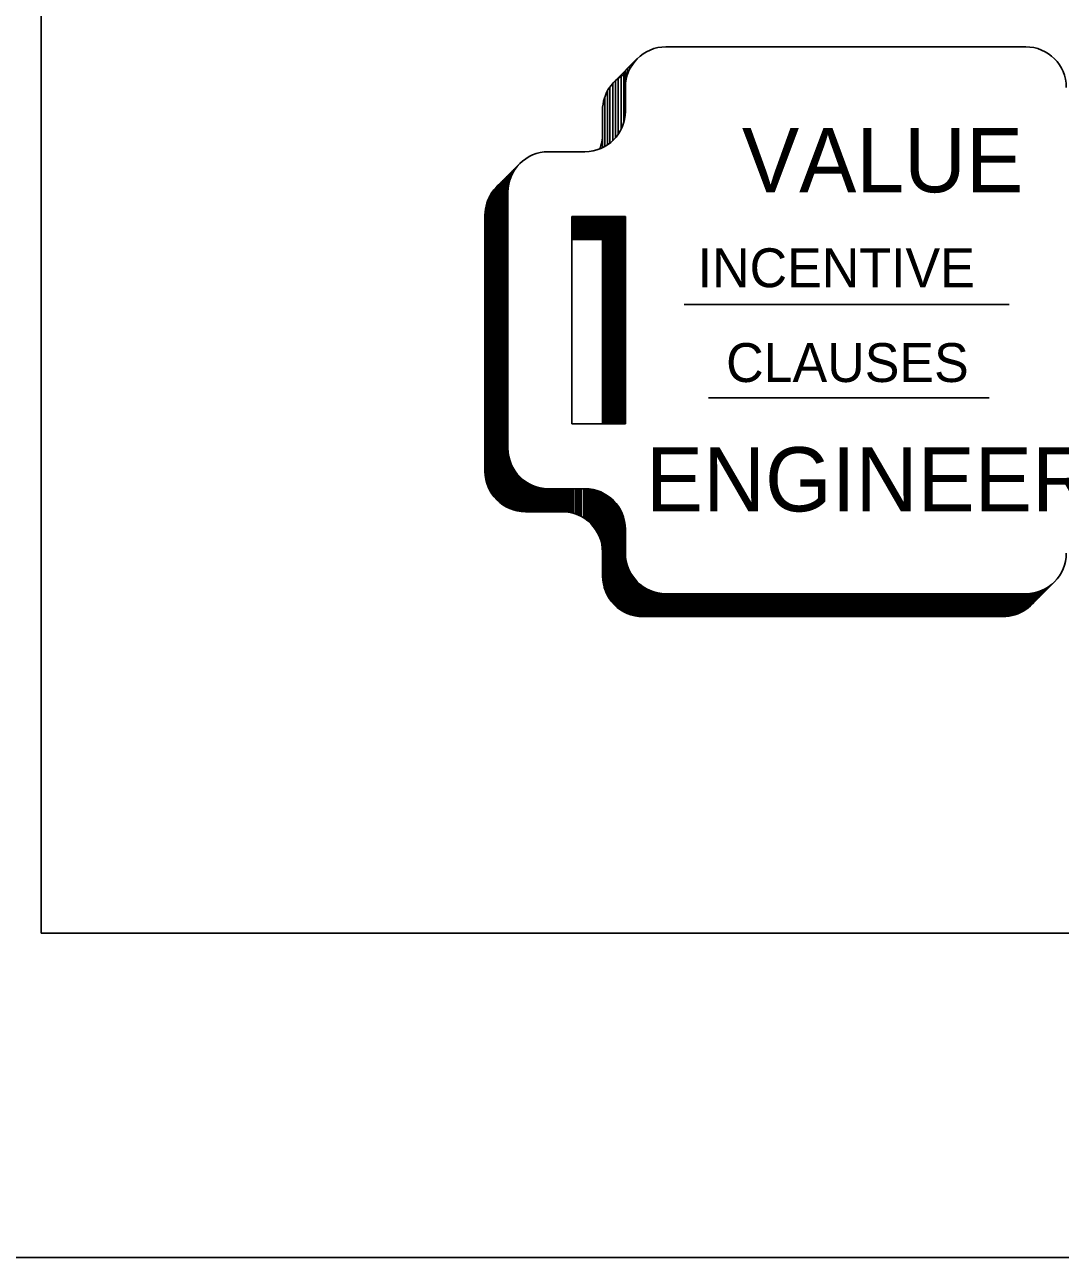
# Model space of a CAD drawing. Extents: x -11983 to -11903, y -13969.5 to -13913.5.
# Drawn here: x -11980.063 to -11976.865, y -13969.481 to -13965.677 of the extents above; entities that cross this region are included whole.
import ezdxf

# ---------------------------------------------------------------- set-up
doc = ezdxf.new("R2010")
doc.units = 0
doc.layers.add('Level 1', color=7, linetype='Continuous')
doc.layers.add('Level 2', color=7, linetype='Continuous')

msp = doc.modelspace()

# ---------------------------------------------------------------- linework, layer by layer
at = {"layer": 'Level 1'}
for points in [[(-11983.0122, -13913.481), (-11903.0122, -13913.481), (-11903.0122, -13969.481), (-11983.0122, -13969.481)], [(-11980.0122, -13914.481), (-11904.0122, -13914.481), (-11904.0122, -13968.481), (-11980.0122, -13968.481)]]:
    msp.add_lwpolyline(points, close=True, dxfattribs=at)
at = {"layer": 'Level 2'}
for p, q in [((-11976.9721, -13965.7456), (-11978.0831, -13965.7456)), ((-11978.2423, -13965.8529), (-11978.1716, -13965.7821)), ((-11978.1956, -13965.8161), (-11978.1956, -13965.8061)), ((-11978.1893, -13965.8049), (-11978.1893, -13965.7999)), ((-11978.1841, -13965.7969), (-11978.1841, -13965.7946)), ((-11978.2306, -13965.8411), (-11978.2306, -13966.0159)), ((-11978.2216, -13965.8321), (-11978.2216, -13966.0009)), ((-11978.2131, -13965.8236), (-11978.2131, -13965.9794)), ((-11978.2081, -13965.8706), (-11978.2081, -13965.8186)), ((-11978.2021, -13965.8324), (-11978.2021, -13965.8126)), ((-11978.2636, -13965.8816), (-11978.2636, -13966.0484)), ((-11978.2558, -13965.8691), (-11978.2558, -13966.0426)), ((-11978.2473, -13965.8584), (-11978.2473, -13966.0354)), ((-11978.2391, -13965.8496), (-11978.2391, -13966.0269)), ((-11978.2081, -13965.8706), (-11978.2081, -13965.9444)), ((-11978.2721, -13965.9009), (-11978.2721, -13966.0534)), ((-11978.2788, -13965.9414), (-11978.2788, -13966.0569)), ((-11978.3331, -13966.0694), (-11978.4461, -13966.0694)), ((-11978.6053, -13966.1766), (-11978.5346, -13966.1059)), ((-11978.5761, -13966.1474), (-11978.5761, -13967.1651)), ((-11978.5738, -13966.1451), (-11978.5738, -13967.1664)), ((-11978.5711, -13966.1944), (-11978.5711, -13966.1424)), ((-11978.5683, -13966.1684), (-11978.5683, -13966.1396)), ((-11978.5648, -13966.1554), (-11978.5648, -13966.1361)), ((-11978.5621, -13966.1479), (-11978.5621, -13966.1334)), ((-11978.5596, -13966.1421), (-11978.5596, -13966.1309)), ((-11978.5573, -13966.1374), (-11978.5573, -13966.1286)), ((-11978.5548, -13966.1326), (-11978.5548, -13966.1261)), ((-11978.5523, -13966.1286), (-11978.5523, -13966.1236)), ((-11978.5498, -13966.1246), (-11978.5498, -13966.1211)), ((-11978.5473, -13966.1211), (-11978.5473, -13966.1186)), ((-11978.6116, -13966.1836), (-11978.6116, -13967.1366)), ((-11978.6083, -13966.1799), (-11978.6083, -13967.1404)), ((-11978.6048, -13966.1764), (-11978.6048, -13967.1439)), ((-11978.6006, -13966.1719), (-11978.6006, -13967.1479)), ((-11978.5976, -13966.1689), (-11978.5976, -13967.1506)), ((-11978.5943, -13966.1656), (-11978.5943, -13967.1531)), ((-11978.5903, -13966.1616), (-11978.5903, -13967.1561)), ((-11978.5861, -13966.1574), (-11978.5861, -13967.1591)), ((-11978.5826, -13966.1539), (-11978.5826, -13967.1614)), ((-11978.5793, -13966.1506), (-11978.5793, -13967.1634)), ((-11978.6346, -13966.2231), (-11978.6346, -13967.0971)), ((-11978.6306, -13966.2134), (-11978.6306, -13967.1069)), ((-11978.6273, -13966.2066), (-11978.6273, -13967.1136)), ((-11978.6233, -13966.1996), (-11978.6233, -13967.1206)), ((-11978.6193, -13966.1936), (-11978.6193, -13967.1266)), ((-11978.6151, -13966.1879), (-11978.6151, -13967.1324)), ((-11978.5711, -13966.1944), (-11978.5711, -13966.9844)), ((-11978.6383, -13966.2359), (-11978.6383, -13967.0844)), ((-11978.6418, -13966.2651), (-11978.6418, -13967.0551)), ((-11978.2081, -13966.2694), (-11978.3736, -13966.2694)), ((-11978.3736, -13966.9094), (-11978.3736, -13966.2694)), ((-11978.2081, -13966.2726), (-11978.3736, -13966.2726)), ((-11978.2081, -13966.2759), (-11978.3736, -13966.2759)), ((-11978.2081, -13966.2796), (-11978.3736, -13966.2796)), ((-11978.2081, -13966.2834), (-11978.3736, -13966.2834)), ((-11978.2081, -13966.2874), (-11978.3736, -13966.2874)), ((-11978.2081, -13966.2911), (-11978.3736, -13966.2911)), ((-11978.2081, -13966.2949), (-11978.3736, -13966.2949)), ((-11978.2081, -13966.2989), (-11978.3736, -13966.2989)), ((-11978.2081, -13966.2694), (-11978.2788, -13966.3401)), ((-11978.2081, -13966.9094), (-11978.2081, -13966.2694)), ((-11978.2081, -13966.3024), (-11978.3736, -13966.3024)), ((-11978.2081, -13966.3061), (-11978.3736, -13966.3061)), ((-11978.2081, -13966.3099), (-11978.3736, -13966.3099)), ((-11978.2081, -13966.3134), (-11978.3736, -13966.3134)), ((-11978.2081, -13966.3169), (-11978.3736, -13966.3169)), ((-11978.2081, -13966.3199), (-11978.3736, -13966.3199)), ((-11978.2081, -13966.3236), (-11978.3736, -13966.3236)), ((-11978.2081, -13966.3266), (-11978.3736, -13966.3266)), ((-11978.2081, -13966.3299), (-11978.3736, -13966.3299)), ((-11978.2081, -13966.3329), (-11978.3736, -13966.3329)), ((-11978.2081, -13966.3366), (-11978.3736, -13966.3366)), ((-11978.2753, -13966.9094), (-11978.2753, -13966.3366)), ((-11978.2726, -13966.9094), (-11978.2726, -13966.3366)), ((-11978.2696, -13966.9094), (-11978.2696, -13966.3366)), ((-11978.2671, -13966.9094), (-11978.2671, -13966.3366)), ((-11978.2633, -13966.9094), (-11978.2633, -13966.3366)), ((-11978.2601, -13966.9094), (-11978.2601, -13966.3366)), ((-11978.2566, -13966.9094), (-11978.2566, -13966.3366)), ((-11978.2541, -13966.9094), (-11978.2541, -13966.3366)), ((-11978.2501, -13966.9094), (-11978.2501, -13966.3366)), ((-11978.2468, -13966.9094), (-11978.2468, -13966.3366)), ((-11978.2441, -13966.9094), (-11978.2441, -13966.3366)), ((-11978.2408, -13966.9094), (-11978.2408, -13966.3366)), ((-11978.2376, -13966.9094), (-11978.2376, -13966.3366)), ((-11978.2338, -13966.9094), (-11978.2338, -13966.3366)), ((-11978.2308, -13966.9094), (-11978.2308, -13966.3366)), ((-11978.2278, -13966.9094), (-11978.2278, -13966.3366)), ((-11978.2241, -13966.9094), (-11978.2241, -13966.3366)), ((-11978.2203, -13966.9094), (-11978.2203, -13966.3366)), ((-11978.2166, -13966.9094), (-11978.2166, -13966.3366)), ((-11978.2141, -13966.9094), (-11978.2141, -13966.3366)), ((-11978.2108, -13966.9094), (-11978.2108, -13966.3366)), ((-11978.2788, -13966.3401), (-11978.3736, -13966.3401)), ((-11978.2788, -13966.9094), (-11978.2788, -13966.3401)), ((-11978.0268, -13966.5411), (-11977.0231, -13966.5411)), ((-11977.9513, -13966.8291), (-11977.0851, -13966.8291)), ((-11978.2081, -13966.9094), (-11978.3736, -13966.9094)), ((-11978.5693, -13967.0051), (-11978.5693, -13967.1686)), ((-11978.5653, -13967.0219), (-11978.5653, -13967.1704)), ((-11978.5616, -13967.0321), (-11978.5616, -13967.1719)), ((-11978.5578, -13967.0404), (-11978.5578, -13967.1731)), ((-11978.5533, -13967.0486), (-11978.5533, -13967.1746)), ((-11978.5501, -13967.0536), (-11978.5501, -13967.1756)), ((-11978.5468, -13967.0584), (-11978.5468, -13967.1764)), ((-11978.5426, -13967.0639), (-11978.5426, -13967.1774)), ((-11978.5391, -13967.0679), (-11978.5391, -13967.1781)), ((-11978.5353, -13967.0719), (-11978.5353, -13967.1786)), ((-11978.5316, -13967.0756), (-11978.5316, -13967.1794)), ((-11978.5278, -13967.0789), (-11978.5278, -13967.1796)), ((-11978.5243, -13967.0819), (-11978.5243, -13967.1799)), ((-11978.5201, -13967.0851), (-11978.5201, -13967.1801)), ((-11978.5163, -13967.0879), (-11978.5163, -13967.1801)), ((-11978.5126, -13967.0901), (-11978.5126, -13967.1801)), ((-11978.5088, -13967.0924), (-11978.5088, -13967.1801)), ((-11978.5043, -13967.0949), (-11978.5043, -13967.1801)), ((-11978.5011, -13967.0966), (-11978.5011, -13967.1801)), ((-11978.4991, -13967.0976), (-11978.4991, -13967.1801)), ((-11978.4958, -13967.0991), (-11978.4958, -13967.1801)), ((-11978.4926, -13967.1004), (-11978.4926, -13967.1801)), ((-11978.4886, -13967.1019), (-11978.4886, -13967.1801)), ((-11978.4846, -13967.1034), (-11978.4846, -13967.1801)), ((-11978.4808, -13967.1044), (-11978.4808, -13967.1801)), ((-11978.4758, -13967.1059), (-11978.4758, -13967.1801)), ((-11978.4713, -13967.1069), (-11978.4713, -13967.1801)), ((-11978.4676, -13967.1076), (-11978.4676, -13967.1801)), ((-11978.4648, -13967.1079), (-11978.4648, -13967.1801)), ((-11978.4611, -13967.1084), (-11978.4611, -13967.1801)), ((-11978.4578, -13967.1089), (-11978.4578, -13967.1801)), ((-11978.4551, -13967.1091), (-11978.4551, -13967.1801)), ((-11978.4516, -13967.1094), (-11978.4516, -13967.1801)), ((-11978.4476, -13967.1094), (-11978.4476, -13967.1801)), ((-11978.4461, -13967.1094), (-11978.3331, -13967.1094)), ((-11978.4438, -13967.1094), (-11978.4438, -13967.1801)), ((-11978.4396, -13967.1094), (-11978.4396, -13967.1801)), ((-11978.4353, -13967.1094), (-11978.4353, -13967.1801)), ((-11978.4316, -13967.1094), (-11978.4316, -13967.1801)), ((-11978.4266, -13967.1094), (-11978.4266, -13967.1801)), ((-11978.4223, -13967.1094), (-11978.4223, -13967.1801)), ((-11978.4186, -13967.1094), (-11978.4186, -13967.1801)), ((-11978.4143, -13967.1094), (-11978.4143, -13967.1801)), ((-11978.4096, -13967.1094), (-11978.4096, -13967.1801)), ((-11978.4051, -13967.1094), (-11978.4051, -13967.1801)), ((-11978.4003, -13967.1094), (-11978.4003, -13967.1801)), ((-11978.3956, -13967.1094), (-11978.3956, -13967.1801)), ((-11978.3901, -13967.1094), (-11978.3901, -13967.1809)), ((-11978.3863, -13967.1094), (-11978.3863, -13967.1814)), ((-11978.3831, -13967.1094), (-11978.3831, -13967.1819)), ((-11978.3798, -13967.1094), (-11978.3798, -13967.1824)), ((-11978.3746, -13967.1094), (-11978.3746, -13967.1836)), ((-11978.3691, -13967.1094), (-11978.3691, -13967.1851)), ((-11978.3633, -13967.1094), (-11978.3633, -13967.1869)), ((-11978.3578, -13967.1094), (-11978.3578, -13967.1889)), ((-11978.3531, -13967.1094), (-11978.3531, -13967.1909)), ((-11978.3476, -13967.1094), (-11978.3476, -13967.1934)), ((-11978.3433, -13967.1094), (-11978.3433, -13967.1956)), ((-11978.3368, -13967.1094), (-11978.3368, -13967.1996)), ((-11978.3316, -13967.1094), (-11978.3316, -13967.2031)), ((-11978.3288, -13967.1094), (-11978.3288, -13967.2051)), ((-11978.3241, -13967.1094), (-11978.3241, -13967.2089)), ((-11978.3203, -13967.1101), (-11978.3203, -13967.2121)), ((-11978.3163, -13967.1106), (-11978.3163, -13967.2159)), ((-11978.3126, -13967.1111), (-11978.3126, -13967.2196)), ((-11978.3098, -13967.1116), (-11978.3098, -13967.2226)), ((-11978.3056, -13967.1124), (-11978.3056, -13967.2279)), ((-11978.3013, -13967.1134), (-11978.3013, -13967.2336)), ((-11978.2968, -13967.1146), (-11978.2968, -13967.2406)), ((-11978.2926, -13967.1161), (-11978.2926, -13967.2481)), ((-11978.2888, -13967.1174), (-11978.2888, -13967.2561)), ((-11978.2848, -13967.1191), (-11978.2848, -13967.2669)), ((-11978.2806, -13967.1209), (-11978.2806, -13967.2844)), ((-11978.2773, -13967.1224), (-11978.2773, -13967.3981)), ((-11978.2733, -13967.1246), (-11978.2733, -13967.4156)), ((-11978.2693, -13967.1269), (-11978.2693, -13967.4266)), ((-11978.2656, -13967.1291), (-11978.2656, -13967.4349)), ((-11978.2618, -13967.1316), (-11978.2618, -13967.4419)), ((-11978.2581, -13967.1344), (-11978.2581, -13967.4479)), ((-11978.2538, -13967.1376), (-11978.2538, -13967.4539)), ((-11978.2506, -13967.1404), (-11978.2506, -13967.4581)), ((-11978.2468, -13967.1439), (-11978.2468, -13967.4624)), ((-11978.2436, -13967.1471), (-11978.2436, -13967.4659)), ((-11978.2396, -13967.1514), (-11978.2396, -13967.4699)), ((-11978.2358, -13967.1559), (-11978.2358, -13967.4731)), ((-11978.2316, -13967.1614), (-11978.2316, -13967.4769)), ((-11978.2276, -13967.1674), (-11978.2276, -13967.4799)), ((-11978.2243, -13967.1726), (-11978.2243, -13967.4821)), ((-11978.5168, -13967.1801), (-11978.4038, -13967.1801)), ((-11978.2213, -13967.1784), (-11978.2213, -13967.4841)), ((-11978.2188, -13967.1836), (-11978.2188, -13967.4856)), ((-11978.2156, -13967.1916), (-11978.2156, -13967.4876)), ((-11978.2128, -13967.2001), (-11978.2128, -13967.4891)), ((-11978.2106, -13967.2096), (-11978.2106, -13967.4904)), ((-11978.2081, -13967.2344), (-11978.2081, -13967.3081)), ((-11978.2788, -13967.3051), (-11978.2788, -13967.3789)), ((-11978.2078, -13967.3161), (-11978.2078, -13967.4916)), ((-11978.2043, -13967.3386), (-11978.2043, -13967.4931)), ((-11978.2011, -13967.3494), (-11978.2011, -13967.4946)), ((-11978.1983, -13967.3566), (-11978.1983, -13967.4956)), ((-11978.1953, -13967.3631), (-11978.1953, -13967.4969)), ((-11978.1928, -13967.3679), (-11978.1928, -13967.4976)), ((-11978.1893, -13967.3739), (-11978.1893, -13967.4986)), ((-11978.1861, -13967.3789), (-11978.1861, -13967.4996)), ((-11978.1826, -13967.3839), (-11978.1826, -13967.5006)), ((-11978.1801, -13967.3869), (-11978.1801, -13967.5011)), ((-11978.1766, -13967.3911), (-11978.1766, -13967.5019)), ((-11978.1746, -13967.3934), (-11978.1746, -13967.5021)), ((-11978.1718, -13967.3961), (-11978.1718, -13967.5026)), ((-11978.1688, -13967.3991), (-11978.1688, -13967.5029)), ((-11978.1666, -13967.4011), (-11978.1666, -13967.5031)), ((-11978.1651, -13967.4024), (-11978.1651, -13967.5034)), ((-11978.1633, -13967.4039), (-11978.1633, -13967.5036)), ((-11976.9543, -13967.4674), (-11976.8836, -13967.3966)), ((-11978.1606, -13967.4061), (-11978.1606, -13967.5036)), ((-11978.1571, -13967.4089), (-11978.1571, -13967.5036)), ((-11978.1531, -13967.4116), (-11978.1531, -13967.5036)), ((-11978.1496, -13967.4139), (-11978.1496, -13967.5036)), ((-11978.1456, -13967.4164), (-11978.1456, -13967.5036)), ((-11978.1418, -13967.4184), (-11978.1418, -13967.5036)), ((-11978.1381, -13967.4204), (-11978.1381, -13967.5036)), ((-11978.1351, -13967.4219), (-11978.1351, -13967.5036)), ((-11978.1316, -13967.4234), (-11978.1316, -13967.5036)), ((-11978.1276, -13967.4249), (-11978.1276, -13967.5036)), ((-11978.1236, -13967.4264), (-11978.1236, -13967.5036)), ((-11978.1196, -13967.4276), (-11978.1196, -13967.5036)), ((-11978.1153, -13967.4289), (-11978.1153, -13967.5036)), ((-11978.1108, -13967.4301), (-11978.1108, -13967.5036)), ((-11978.1073, -13967.4309), (-11978.1073, -13967.5036)), ((-11978.1028, -13967.4316), (-11978.1028, -13967.5036)), ((-11978.0988, -13967.4321), (-11978.0988, -13967.5036)), ((-11978.0948, -13967.4326), (-11978.0948, -13967.5036)), ((-11978.0901, -13967.4329), (-11978.0901, -13967.5036)), ((-11978.0861, -13967.4331), (-11978.0861, -13967.5036)), ((-11978.0861, -13967.4349), (-11977.0428, -13967.4349)), ((-11978.0861, -13967.4361), (-11977.0428, -13967.4361)), ((-11978.0861, -13967.4374), (-11977.0428, -13967.4374)), ((-11978.0861, -13967.4391), (-11977.0428, -13967.4391)), ((-11978.0861, -13967.4411), (-11977.0428, -13967.4411)), ((-11978.0831, -13967.4331), (-11976.9721, -13967.4331)), ((-11977.0428, -13967.5039), (-11977.0428, -13967.4331)), ((-11977.0401, -13967.5039), (-11977.0401, -13967.4331)), ((-11977.0381, -13967.5039), (-11977.0381, -13967.4331)), ((-11977.0361, -13967.5036), (-11977.0361, -13967.4331)), ((-11977.0328, -13967.5034), (-11977.0328, -13967.4331)), ((-11977.0303, -13967.5031), (-11977.0303, -13967.4331)), ((-11977.0273, -13967.5029), (-11977.0273, -13967.4331)), ((-11977.0248, -13967.5026), (-11977.0248, -13967.4331)), ((-11977.0221, -13967.5021), (-11977.0221, -13967.4331)), ((-11977.0198, -13967.5016), (-11977.0198, -13967.4331)), ((-11977.0168, -13967.5011), (-11977.0168, -13967.4331)), ((-11977.0141, -13967.5006), (-11977.0141, -13967.4331)), ((-11977.0113, -13967.4999), (-11977.0113, -13967.4331)), ((-11977.0078, -13967.4989), (-11977.0078, -13967.4331)), ((-11977.0041, -13967.4976), (-11977.0041, -13967.4331)), ((-11977.0011, -13967.4966), (-11977.0011, -13967.4331)), ((-11976.9981, -13967.4956), (-11976.9981, -13967.4331)), ((-11976.9948, -13967.4944), (-11976.9948, -13967.4331)), ((-11976.9916, -13967.4929), (-11976.9916, -13967.4331)), ((-11976.9888, -13967.4916), (-11976.9888, -13967.4331)), ((-11976.9851, -13967.4896), (-11976.9851, -13967.4331)), ((-11976.9813, -13967.4876), (-11976.9813, -13967.4331)), ((-11976.9778, -13967.4856), (-11976.9778, -13967.4331)), ((-11976.9743, -13967.4834), (-11976.9743, -13967.4331)), ((-11976.9708, -13967.4811), (-11976.9708, -13967.4331)), ((-11976.9676, -13967.4786), (-11976.9676, -13967.4331)), ((-11976.9641, -13967.4759), (-11976.9641, -13967.4331)), ((-11976.9603, -13967.4729), (-11976.9603, -13967.4326)), ((-11976.9568, -13967.4696), (-11976.9568, -13967.4321)), ((-11976.9538, -13967.4669), (-11976.9538, -13967.4319)), ((-11976.9506, -13967.4636), (-11976.9506, -13967.4314)), ((-11976.9481, -13967.4611), (-11976.9481, -13967.4309)), ((-11976.9451, -13967.4581), (-11976.9451, -13967.4301)), ((-11976.9426, -13967.4556), (-11976.9426, -13967.4296)), ((-11976.9398, -13967.4529), (-11976.9398, -13967.4289)), ((-11976.9368, -13967.4499), (-11976.9368, -13967.4281)), ((-11976.9348, -13967.4479), (-11976.9348, -13967.4274)), ((-11976.9323, -13967.4454), (-11976.9323, -13967.4266)), ((-11976.9301, -13967.4431), (-11976.9301, -13967.4259)), ((-11976.9276, -13967.4406), (-11976.9276, -13967.4249)), ((-11976.9261, -13967.4391), (-11976.9261, -13967.4244)), ((-11976.9231, -13967.4361), (-11976.9231, -13967.4231)), ((-11976.9208, -13967.4339), (-11976.9208, -13967.4221)), ((-11976.9183, -13967.4314), (-11976.9183, -13967.4209)), ((-11976.9156, -13967.4286), (-11976.9156, -13967.4196)), ((-11976.9133, -13967.4264), (-11976.9133, -13967.4184)), ((-11976.9111, -13967.4241), (-11976.9111, -13967.4171)), ((-11976.9088, -13967.4219), (-11976.9088, -13967.4159)), ((-11976.9063, -13967.4194), (-11976.9063, -13967.4144)), ((-11976.9038, -13967.4169), (-11976.9038, -13967.4129)), ((-11976.9016, -13967.4146), (-11976.9016, -13967.4114)), ((-11976.8993, -13967.4124), (-11976.8993, -13967.4099)), ((-11976.8971, -13967.4101), (-11976.8971, -13967.4081)), ((-11978.0861, -13967.4434), (-11977.0428, -13967.4434)), ((-11978.0861, -13967.4456), (-11977.0428, -13967.4456)), ((-11978.0861, -13967.4476), (-11977.0428, -13967.4476)), ((-11978.0861, -13967.4499), (-11977.0428, -13967.4499)), ((-11978.0861, -13967.4521), (-11977.0428, -13967.4521)), ((-11978.0861, -13967.4544), (-11977.0428, -13967.4544)), ((-11978.0861, -13967.4566), (-11977.0428, -13967.4566)), ((-11978.0861, -13967.4589), (-11977.0428, -13967.4589)), ((-11978.0861, -13967.4609), (-11977.0428, -13967.4609)), ((-11978.0861, -13967.4631), (-11977.0428, -13967.4631)), ((-11978.0861, -13967.4651), (-11977.0428, -13967.4651)), ((-11978.0861, -13967.4671), (-11977.0428, -13967.4671)), ((-11978.0861, -13967.4694), (-11977.0428, -13967.4694)), ((-11978.0861, -13967.4716), (-11977.0428, -13967.4716)), ((-11978.0861, -13967.4741), (-11977.0428, -13967.4741)), ((-11978.0861, -13967.4766), (-11977.0428, -13967.4766)), ((-11978.0861, -13967.4791), (-11977.0428, -13967.4791)), ((-11978.1538, -13967.5039), (-11977.0428, -13967.5039)), ((-11978.0861, -13967.4814), (-11977.0428, -13967.4814)), ((-11978.0861, -13967.4841), (-11977.0428, -13967.4841)), ((-11978.0861, -13967.4866), (-11977.0428, -13967.4866)), ((-11978.0861, -13967.4894), (-11977.0428, -13967.4894)), ((-11978.0861, -13967.4921), (-11977.0428, -13967.4921)), ((-11978.0861, -13967.4951), (-11977.0428, -13967.4951)), ((-11978.0861, -13967.4979), (-11977.0428, -13967.4979)), ((-11978.0861, -13967.5006), (-11977.0428, -13967.5006))]:
    msp.add_line(p, q, dxfattribs=at)
for centre, start, end in [((-11978.0831, -13965.8706), 90, 180), ((-11976.9721, -13965.8706), 0, 90), ((-11978.1538, -13965.9414), 111.4079, 180), ((-11978.3331, -13965.9444), 270, 0), ((-11978.4038, -13966.0151), 338.5921, 0), ((-11978.4461, -13966.1944), 90, 180), ((-11978.5168, -13966.2651), 111.4079, 180), ((-11978.4461, -13966.9844), 180, 270), ((-11978.5168, -13967.0551), 180, 270), ((-11978.3331, -13967.2344), 0, 90), ((-11978.4038, -13967.3051), 0, 90), ((-11978.0831, -13967.3081), 180, 270), ((-11976.9721, -13967.3081), 270, 0), ((-11978.1538, -13967.3789), 180, 270), ((-11977.0428, -13967.3789), 270, 338.5921)]:
    msp.add_arc(centre, 0.125, start, end, dxfattribs=at)

# ---------------------------------------------------------------- texts
for s, height, p in [('VALUE', 0.19799, (-11977.8483, -13966.1944)), ('INCENTIVE', 0.11999, (-11977.9853, -13966.4874)), ('CLAUSES', 0.11999, (-11977.8973, -13966.7799)), ('ENGINEERING', 0.197985, (-11978.1448, -13967.1791))]:
    msp.add_text(s, height=height, dxfattribs=at).set_placement(p)

doc.saveas('drawing.dxf')
